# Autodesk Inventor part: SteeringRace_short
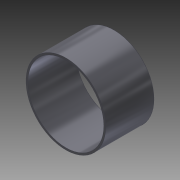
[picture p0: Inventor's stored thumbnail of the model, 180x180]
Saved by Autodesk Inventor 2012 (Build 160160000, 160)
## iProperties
Created: 2010-12
Part Number: SteeringRace_short
Document SubType Name: Modeling
Designer: Alex
Density: 7.84 g/cm^3
Material: Steel, High Strength Low Alloy
Mass: 18.8121 g
Surface Area: 56.0605 cm^2
Volume: 2.3995 cm^3
Author: Alex
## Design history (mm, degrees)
sketch "Sketch1"
  geometry: C1 r 19.05 at (0, 0); C2 r 18.161 at (0, 0); 1 further point
  constraints: 2 centre point
  dimensions: "d0" = 38.1 diameter of C1; "d1" = 36.322 diameter of C2
extrude "Extrusion1" new body sketch "Sketch1" distance "d2" = 23.0886; taper "d3" = 0 deg
body "Solid1"
